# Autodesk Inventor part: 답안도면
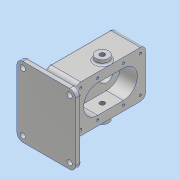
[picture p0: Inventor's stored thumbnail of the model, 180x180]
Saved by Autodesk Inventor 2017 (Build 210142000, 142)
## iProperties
Part Number: 답안도면
Material: 알루미늄 6061
Document SubType Name: Modeling
Designer: MRC
Density: 2.7 g/cm^3
Appearance: 알루미늄 - 평지
Mass: 1472.01 g
Surface Area: 820.338 cm^2
Volume: 545.188 cm^3
Author: MRC
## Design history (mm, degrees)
sketch "스케치1"
  geometry: L1 (-26.5, 60)-(-26.5, -60); L2 (-26.5, -60)-(26.5, -60); L3 (-26.5, 60)-(26.5, 60); L4 (26.5, 60)-(26.5, -60); 3 further points
  constraints: 8 end point, 2 horizontal, 2 midpoint, 1 horizontal alignment, 1 vertical, 1 vertical alignment
  dimensions: "d0" = 120 distance of L1.start L1.end; "d1" = 53 distance of L1.end L2.end; "d2" = 53 distance of L1.start L3.end
extrude "돌출1" new body sketch "스케치1" stored distance "d3" = 80; taper "d4" = 0 deg
sketch "스케치2"
  geometry: L1 (40, 60)-(40, 82); L2 (40, 60)-(40, 38); L3 (40, 82)-(40, 38); L4 (16, 82)-(16, 38); L5 (64, 38)-(64, 82); A1 r 24 centre (40, 82) between (64, 82) and (16, 82); A2 r 24 centre (40, 38) between (16, 38) and (64, 38); 1 further point
  constraints: 12 end point, 4 point on circle, 4 tangent, 3 vertical, 2 centre point, 1 midpoint, 1 parallel
  dimensions: "d5" = 22 distance of L1.start L1.end; "d6" = 22 distance of L1.start L2.end; "d7" = 48 diameter of A2
extrude "돌출2" cut sketch "스케치2" distance "d8" = 29; taper "d9" = 0 deg
sketch "스케치3"
  geometry: C1 r 12.5 at (40, 82); C2 r 12.5 at (40, 38); A1 r 24 centre (40, 38) between (16, 38) and (64, 38) reference; A2 r 24 centre (40, 82) between (64, 82) and (16, 82) reference; 1 further point
  constraints: 2 centre point, 2 coincident
  dimensions: "d10" = 25 diameter of C1; "d11" = 25 diameter of C2
extrude "돌출3" cut sketch "스케치3" distance "d12" = 15; taper "d13" = 0 deg
sketch "스케치4"
  geometry: L1 (-40, 60)-(-40, 82); C1 r 19 at (-40, 82)
  constraints: 2 end point, 1 centre point, 1 coincident, 1 vertical
  dimensions: "d14" = 22 distance of L1.start L1.end; "d15" = 38 diameter of C1
extrude "돌출4" join sketch "스케치4" distance "d16" = 17; taper "d17" = 0 deg
sketch "스케치5"
  geometry: C1 r 19 at (0, 0) reference; C2 r 14 at (0, 0); 1 further point
  constraints: 1 centre point, 1 coincident
  dimensions: "d18" = 28 diameter of C2
extrude "돌출5" cut sketch "스케치5" distance "d19" = 7.3; taper "d20" = 0 deg
sketch "스케치6"
  geometry: C1 r 12.5 at (0, 0) reference; C2 r 8.5 at (0, 0); 1 further point
  constraints: 1 centre point, 1 coincident
  dimensions: "d21" = 17 diameter of C2
extrude "돌출6" cut sketch "스케치6" distance "d22" = 18.7; taper "d23" = 0 deg
node "작업 평면1"
sketch "스케치7"
  geometry: L1 (-56.5, -60)-(43.5, -60); L2 (43.5, -60)-(43.5, 60); L3 (43.5, 60)-(-56.5, 60); L4 (-56.5, 60)-(-56.5, -60); L5 (43.5, -19)-(43.5, 19) reference; 3 further points
  constraints: 8 end point, 3 midpoint, 2 parallel, 1 horizontal, 1 horizontal alignment, 1 perpendicular
  dimensions: "d25" = 100 distance of L3.end L2.end; "d26" = 120 distance of L2.end L1.end
extrude "돌출7" join sketch "스케치7" distance "d27" = 10; taper "d28" = 0 deg
fillet "모깎기1" dims "d33" = 9
fillet "모깎기2" dims "d34" = 3
sketch "스케치9"
  geometry: L1 (-26.5, -80)-(-14.953, -60); L2 (26.5, -80)-(14.953, -60); L3 (-43.5, -80)-(56.5, -80) reference; L4 (-43.5, -90)-(-43.5, -80) reference; L5 (-23.5, -60)-(26.5, -60) reference; 1 further point
  constraints: 4 end point, 4 point on line
  dimensions: "d35" = 60 deg angle of L1 L3; "d36" = 60 deg angle of L3 L2; "d37" = 17 distance from line of L1.start L4; "d38" = 53 distance of L2.start L1.start
extrude "돌출8" join sketch "스케치9" stored distance "d39" = 48; taper "d40" = 0 deg
sketch "스케치10"
  geometry: L1 (-26.5, 51)-(-26.5, -51) reference; C1 r 11 at (-12.5, 0); 1 further point
  constraints: 1 centre point, 1 horizontal alignment
  dimensions: "d41" = 22 diameter of C1; "d42" = 14 distance from line of C1.centre L1
extrude "돌출9" join sketch "스케치10" distance "d43" = 8; taper "d44" = 0 deg
hole "구멍1" diameter "d47" = 8.376; stored, may be unused: countersink angle "d51" = 90 deg, drill point angle "d53" = 118 deg; dims "d45" = 10, "d46" = 10, "d48" = 20, "d49" = 4, "d50" = 2, "d52" = 27.3
fillet "모깎기3" dims "d54" = 3
fillet "모깎기4" dims "d55" = 10
fillet "모깎기5" dims "d56" = 3
sketch "스케치11"
  geometry: A1 r 7 centre (-33.5, -50) between (-40.5, -50) and (-33.5, -57) reference; A2 r 7 centre (46.5, -50) between (46.5, -57) and (53.5, -50) reference; A3 r 7 centre (46.5, 50) between (53.5, 50) and (46.5, 57) reference; A4 r 7 centre (-33.5, 50) between (-33.5, 57) and (-40.5, 50) reference; 5 further points
  constraints: 4 coincident
hole "구멍2" sketch "스케치11" at (-33.5, 50), (46.5, 50), (46.5, -50), (-33.5, -50) diameter "d57" = 9; stored, may be unused: countersink angle "d61" = 90 deg, drill point angle "d63" = 118 deg; dims "d58" = 20, "d59" = 4, "d60" = 2, "d62" = 27.3
chamfer "모따기1" distance "d64" = 0.7; stored, may be unused: second distance "d65" = 2, angle "d66" = 30 deg
chamfer "모따기2" distance "d67" = 1; stored, may be unused: second distance "d68" = 2, angle "d69" = 30 deg
sketch "스케치12"
  geometry: L1 (-33.5, -60)-(46.5, -60) reference; L2 (56.5, -50)-(56.5, 50) reference; 2 further points
  constraints: 1 other
  dimensions: "d70" = 60 distance from line of L1 point (46.5, 0); "d71" = 10 distance from line of L2 point (46.5, 0)
feature "엠보싱1" sketch "스케치12" dims "d0" = 120, "d1" = 53, "d2" = 53, "d72" = 0.5, "d73" = 0
sketch "스케치13"
  geometry: A1 r 9 centre (62, -111) between (62, -120) and (71, -111) reference; A2 r 9 centre (62, -9) between (71, -9) and (62, 0) reference; A3 r 9 centre (0, -9) between (0, 0) and (-9, -9) reference; A4 r 9 centre (0, -111) between (-9, -111) and (0, -120) reference; 9 further points
  constraints: 4 coincident, 4 vertical alignment, 2 horizontal alignment
  dimensions: "d74" = 29 distance of point (0, -38) point (0, -9); "d75" = 29 distance of point (0, -111) point (0, -82)
hole "구멍3" sketch "스케치13" at (0, -9), (62, -9), (0, -111), (62, -111), (0, -38), (0, -82), (62, -38), (62, -82) diameter "d76" = 4.134; stored, may be unused: countersink angle "d80" = 90 deg, drill point angle "d82" = 118 deg; dims "d77" = 10, "d78" = 4, "d79" = 2, "d81" = 12
fillet "모깎기6" dims "d83" = 0.5
node "솔리드1"
mirror "미러1"
